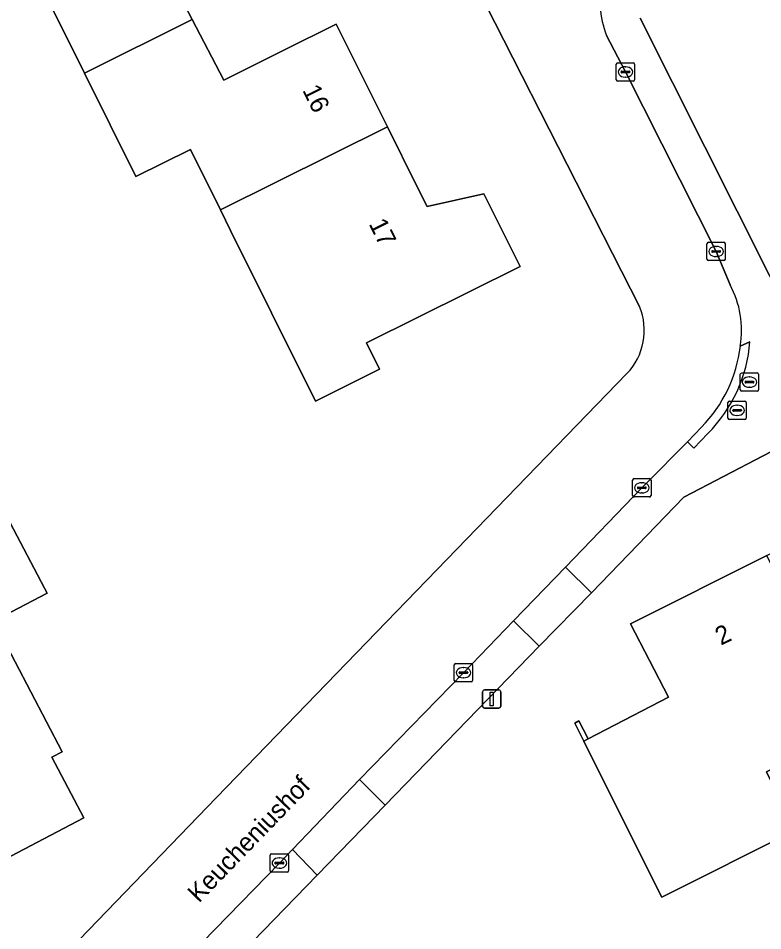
# Model space of a CAD drawing. Extents: x 162722 to 165104, y 384719 to 386284.
# Drawn here: x 163739.56 to 163780.16, y 384930.12 to 384979.9 of the extents above; entities that cross this region are included whole.
import ezdxf

# ---------------------------------------------------------------- set-up
doc = ezdxf.new("R2010")
doc.units = 0
for name, color, linetype in [('IMGEO_Erf', 7, 'Continuous'), ('IMGEO_Kolk', 7, 'Continuous'), ('IMGEO_Lichtmast', 7, 'Continuous'), ('IMGEO_Muur', 7, 'Continuous'), ('IMGEO_Openbare_ruimte_label', 7, 'Continuous'), ('IMGEO_Pand', 7, 'Continuous'), ('IMGEO_Pand_nummerreeks', 7, 'Continuous'), ('IMGEO_Parkeervlak_open', 7, 'Continuous'), ('IMGEO_Rijbaan_lokaal_open', 7, 'Continuous'), ('IMGEO_Rioolput', 7, 'Continuous'), ('IMGEO_Voetpad_open', 7, 'Continuous')]:
    doc.layers.add(name, color=color, linetype=linetype)

msp = doc.modelspace()

# ---------------------------------------------------------------- linework, layer by layer
at = {"layer": 'IMGEO_Erf'}
for points in [[(163773.45, 384964.172), (163757.669, 384995.182)], [(163747.308, 384983.144), (163749.036, 384979.836), (163750.763, 384976.531), (163754.038, 384978.16), (163756.905, 384979.586), (163759.69, 384973.984), (163761.287, 384970.773), (163761.856, 384969.629), (163764.958, 384970.319), (163766.926, 384966.361), (163758.55, 384962.196), (163759.265, 384960.758), (163755.768, 384959.019), (163753.371, 384963.839), (163751.144, 384968.317), (163750.581, 384969.45), (163748.947, 384972.736), (163745.975, 384971.259), (163743.164, 384976.913), (163740.366, 384982.54)], [(163773.478, 384979.9), (163782.291, 384962.358), (163782.404, 384962.416), (163802.16, 384972.581), (163804.226, 384968.418), (163784.518, 384958.283), (163775.869, 384953.781), (163770.816, 384948.556), (163767.966, 384945.654), (163759.567, 384936.98), (163755.864, 384933.157), (163744.141, 384921.063)], [(163739.897, 384926.539), (163750.364, 384937.388), (163772.76, 384960.515)]]:
    msp.add_lwpolyline(points, dxfattribs=at)
for points in [[(163774.653, 384931.962), (163772.706, 384935.862), (163770.404, 384940.472), (163769.914, 384941.454), (163770.139, 384941.571), (163770.645, 384940.597), (163775.023, 384942.872), (163772.946, 384946.868), (163780.388, 384950.584), (163787.828, 384954.299), (163788.941, 384952.07), (163791.108, 384947.731), (163796.82, 384950.584), (163794.653, 384954.922), (163794.885, 384955.038), (163797.052, 384950.7), (163800.045, 384944.704), (163790.533, 384939.954), (163788.967, 384943.091), (163785.094, 384941.157), (163780.367, 384938.797), (163781.958, 384935.61)], [(163739.111, 384952.379), (163740.984, 384948.815), (163741.129, 384948.539), (163739.187, 384947.518), (163738.217, 384947.008), (163738.524, 384946.424), (163741.959, 384939.889), (163741.39, 384939.59), (163743.129, 384936.283), (163737.685, 384933.421), (163735.947, 384936.728), (163733.919, 384935.662), (163731.932, 384939.443), (163730.365, 384942.425), (163729.381, 384941.909), (163727.176, 384946.104), (163737.169, 384951.358)]]:
    msp.add_lwpolyline(points, close=True, dxfattribs=at)
msp.add_arc((163770.267, 384962.879), 3.436, 316.5242, 22.1059, dxfattribs=at)
at = {"layer": 'IMGEO_Kolk'}
for p, q in [((163772.176, 384976.545), (163772.176, 384977.397)), ((163772.251, 384977.471), (163773.103, 384977.471)), ((163772.664, 384977.251), (163772.689, 384977.251)), ((163773.177, 384977.397), (163773.177, 384976.545)), ((163772.435, 384976.965), (163772.435, 384976.977)), ((163772.873, 384976.928), (163772.475, 384976.928)), ((163772.478, 384977.014), (163772.876, 384977.014)), ((163772.687, 384976.691), (163772.662, 384976.691)), ((163772.919, 384976.977), (163772.919, 384976.965)), ((163773.103, 384976.471), (163772.251, 384976.471)), ((163777.198, 384967.677), (163778.05, 384967.677)), ((163777.123, 384966.751), (163777.123, 384967.603)), ((163777.382, 384967.171), (163777.382, 384967.183)), ((163777.82, 384967.134), (163777.422, 384967.134)), ((163777.425, 384967.22), (163777.823, 384967.22)), ((163777.611, 384967.457), (163777.636, 384967.457)), ((163777.866, 384967.183), (163777.866, 384967.171)), ((163778.124, 384967.603), (163778.124, 384966.751)), ((163778.05, 384966.677), (163777.198, 384966.677)), ((163777.634, 384966.897), (163777.609, 384966.897)), ((163773.069, 384953.858), (163773.069, 384954.71)), ((163773.144, 384954.784), (163773.996, 384954.784)), ((163774.07, 384954.71), (163774.07, 384953.858)), ((163773.328, 384954.278), (163773.328, 384954.29)), ((163773.766, 384954.241), (163773.368, 384954.241)), ((163773.371, 384954.327), (163773.769, 384954.327)), ((163773.557, 384954.564), (163773.582, 384954.564)), ((163773.812, 384954.29), (163773.812, 384954.278)), ((163773.996, 384953.784), (163773.144, 384953.784)), ((163773.58, 384954.004), (163773.555, 384954.004)), ((163763.34, 384943.773), (163763.34, 384944.625)), ((163763.415, 384944.699), (163764.267, 384944.699)), ((163763.642, 384944.242), (163764.04, 384944.242)), ((163763.828, 384944.479), (163763.853, 384944.479)), ((163764.341, 384944.625), (163764.341, 384943.773)), ((163763.599, 384944.193), (163763.599, 384944.205)), ((163764.037, 384944.156), (163763.639, 384944.156)), ((163763.851, 384943.919), (163763.826, 384943.919)), ((163764.083, 384944.205), (163764.083, 384944.193)), ((163764.267, 384943.699), (163763.415, 384943.699)), ((163753.377, 384934.315), (163754.229, 384934.315)), ((163753.302, 384933.389), (163753.302, 384934.241)), ((163753.561, 384933.809), (163753.561, 384933.821)), ((163753.604, 384933.858), (163754.002, 384933.858)), ((163753.79, 384934.095), (163753.815, 384934.095)), ((163754.045, 384933.821), (163754.045, 384933.809)), ((163754.303, 384934.241), (163754.303, 384933.389)), ((163754.229, 384933.315), (163753.377, 384933.315)), ((163753.999, 384933.772), (163753.601, 384933.772)), ((163753.813, 384933.535), (163753.788, 384933.535))]:
    msp.add_line(p, q, dxfattribs=at)
for points in [[(163772.176, 384976.545), (163772.176, 384977.397)], [(163772.251, 384977.471), (163773.103, 384977.471)], [(163773.177, 384977.397), (163773.177, 384976.545)], [(163773.103, 384976.471), (163772.251, 384976.471)], [(163777.198, 384967.677), (163778.05, 384967.677)], [(163777.123, 384966.751), (163777.123, 384967.603)], [(163778.124, 384967.603), (163778.124, 384966.751)], [(163778.05, 384966.677), (163777.198, 384966.677)], [(163773.069, 384953.858), (163773.069, 384954.71)], [(163773.144, 384954.784), (163773.996, 384954.784)], [(163774.07, 384954.71), (163774.07, 384953.858)], [(163773.996, 384953.784), (163773.144, 384953.784)], [(163763.34, 384943.773), (163763.34, 384944.625)], [(163763.415, 384944.699), (163764.267, 384944.699)], [(163764.341, 384944.625), (163764.341, 384943.773)], [(163764.267, 384943.699), (163763.415, 384943.699)], [(163753.377, 384934.315), (163754.229, 384934.315)], [(163753.302, 384933.389), (163753.302, 384934.241)], [(163754.303, 384934.241), (163754.303, 384933.389)], [(163754.229, 384933.315), (163753.377, 384933.315)]]:
    msp.add_lwpolyline(points, dxfattribs=at)
for centre, radius, start, end in [((163772.253, 384977.395), 0.0765, 91.552, 178.448), ((163772.253, 384977.395), 0.0765, 91.552, 178.448), ((163773.101, 384977.395), 0.0765, 1.552, 88.448), ((163773.101, 384977.395), 0.0765, 1.552, 88.448), ((163772.475, 384976.974), 0.0403, 85.8775, 175.7526), ((163772.472, 384976.964), 0.0366, 178.938, 274.7102), ((163772.876, 384976.971), 0.043, 264.8664, 352.4533), ((163772.88, 384976.976), 0.0386, 1.7309, 96.639), ((163772.253, 384976.547), 0.0765, 181.552, 268.448), ((163772.253, 384976.547), 0.0765, 181.552, 268.448), ((163773.101, 384976.547), 0.0765, 271.552, 358.448), ((163773.101, 384976.547), 0.0765, 271.552, 358.448), ((163777.2, 384967.601), 0.0765, 91.552, 178.448), ((163777.2, 384967.601), 0.0765, 91.552, 178.448), ((163778.048, 384967.601), 0.0765, 1.552, 88.448), ((163778.048, 384967.601), 0.0765, 1.552, 88.448), ((163777.422, 384967.18), 0.0403, 85.8775, 175.7526), ((163777.419, 384967.17), 0.0366, 178.938, 274.7102), ((163777.823, 384967.177), 0.043, 264.8664, 352.4533), ((163777.827, 384967.182), 0.0386, 1.7309, 96.639), ((163777.2, 384966.753), 0.0765, 181.552, 268.448), ((163777.2, 384966.753), 0.0765, 181.552, 268.448), ((163778.048, 384966.753), 0.0765, 271.552, 358.448), ((163778.048, 384966.753), 0.0765, 271.552, 358.448), ((163773.146, 384954.708), 0.0765, 91.552, 178.448), ((163773.146, 384954.708), 0.0765, 91.552, 178.448), ((163773.994, 384954.708), 0.0765, 1.552, 88.448), ((163773.994, 384954.708), 0.0765, 1.552, 88.448), ((163773.368, 384954.287), 0.0403, 85.8775, 175.7526), ((163773.365, 384954.277), 0.0366, 178.938, 274.7102), ((163773.769, 384954.284), 0.043, 264.8664, 352.4533), ((163773.773, 384954.289), 0.0386, 1.7309, 96.639), ((163773.146, 384953.86), 0.0765, 181.552, 268.448), ((163773.146, 384953.86), 0.0765, 181.552, 268.448), ((163773.994, 384953.86), 0.0765, 271.552, 358.448), ((163773.994, 384953.86), 0.0765, 271.552, 358.448), ((163763.417, 384944.623), 0.0765, 91.552, 178.448), ((163763.417, 384944.623), 0.0765, 91.552, 178.448), ((163763.639, 384944.202), 0.0403, 85.8775, 175.7526), ((163764.044, 384944.204), 0.0386, 1.7309, 96.639), ((163764.265, 384944.623), 0.0765, 1.552, 88.448), ((163764.265, 384944.623), 0.0765, 1.552, 88.448), ((163763.417, 384943.775), 0.0765, 181.552, 268.448), ((163763.417, 384943.775), 0.0765, 181.552, 268.448), ((163763.636, 384944.192), 0.0366, 178.938, 274.7102), ((163764.04, 384944.199), 0.043, 264.8664, 352.4533), ((163764.265, 384943.775), 0.0765, 271.552, 358.448), ((163764.265, 384943.775), 0.0765, 271.552, 358.448), ((163753.379, 384934.239), 0.0765, 91.552, 178.448), ((163753.379, 384934.239), 0.0765, 91.552, 178.448), ((163754.227, 384934.239), 0.0765, 1.552, 88.448), ((163754.227, 384934.239), 0.0765, 1.552, 88.448), ((163753.601, 384933.818), 0.0403, 85.8775, 175.7526), ((163753.598, 384933.808), 0.0366, 178.938, 274.7102), ((163754.002, 384933.815), 0.043, 264.8664, 352.4533), ((163754.006, 384933.82), 0.0386, 1.7309, 96.639), ((163753.379, 384933.391), 0.0765, 181.552, 268.448), ((163753.379, 384933.391), 0.0765, 181.552, 268.448), ((163754.227, 384933.391), 0.0765, 271.552, 358.448), ((163754.227, 384933.391), 0.0765, 271.552, 358.448)]:
    msp.add_arc(centre, radius, start, end, dxfattribs=at)
for centre, major_axis, ratio, start_param, end_param in [((163772.663, 384976.971), (-0.387, 0.002), 0.722429, 4.712389, 7.853982), ((163772.688, 384976.971), (-0.39, 0.002), 0.717154, 1.570796, 4.712389), ((163777.61, 384967.177), (-0.387, 0.002), 0.722429, 4.712389, 7.853982), ((163777.635, 384967.177), (-0.39, 0.002), 0.717154, 1.570796, 4.712389), ((163773.556, 384954.284), (-0.387, 0.002), 0.722429, 4.712389, 7.853982), ((163773.581, 384954.284), (-0.39, 0.002), 0.717154, 1.570796, 4.712389), ((163763.827, 384944.199), (-0.387, 0.002), 0.722429, 4.712389, 7.853982), ((163763.852, 384944.199), (-0.39, 0.002), 0.717154, 1.570796, 4.712389), ((163753.789, 384933.815), (-0.387, 0.002), 0.722429, 4.712389, 7.853982), ((163753.814, 384933.815), (-0.39, 0.002), 0.717154, 1.570796, 4.712389)]:
    msp.add_ellipse(centre, major_axis=major_axis, ratio=ratio, start_param=start_param, end_param=end_param, dxfattribs=at)
at = {"layer": 'IMGEO_Lichtmast'}
for p, q in [((163764.983, 384943.264), (163765.773, 384943.264)), ((163765.773, 384943.264), (163764.983, 384943.264)), ((163764.883, 384942.364), (163764.883, 384943.164)), ((163764.883, 384943.164), (163764.883, 384942.364)), ((163765.873, 384943.164), (163765.873, 384942.364)), ((163765.873, 384942.364), (163765.873, 384943.164)), ((163765.773, 384942.264), (163764.983, 384942.264)), ((163764.983, 384942.264), (163765.773, 384942.264))]:
    msp.add_line(p, q, dxfattribs=at)
msp.add_lwpolyline([(163765.303, 384943.139), (163765.453, 384943.139), (163765.453, 384942.389), (163765.303, 384942.389), (163765.303, 384943.139)], dxfattribs=at)
for centre, start, end in [((163764.983, 384943.164), 90, 180), ((163764.983, 384943.164), 90, 180), ((163765.773, 384943.164), 0, 90), ((163765.773, 384943.164), 360, 90), ((163764.983, 384942.364), 180, 270), ((163764.983, 384942.364), 180, 270), ((163765.773, 384942.364), 270, 0), ((163765.773, 384942.364), 270, 0)]:
    msp.add_arc(centre, 0.1, start, end, dxfattribs=at)
at = {"layer": 'IMGEO_Muur'}
msp.add_lwpolyline([(163770.404, 384940.472), (163770.645, 384940.597), (163770.139, 384941.571), (163769.914, 384941.454)], close=True, dxfattribs=at)
at = {"layer": 'IMGEO_Pand'}
for points in [[(163741.448, 384987.316), (163743.137, 384983.918), (163740.366, 384982.54), (163743.164, 384976.913), (163749.036, 384979.836), (163747.308, 384983.144), (163750.717, 384984.839), (163753.45, 384986.198), (163750.625, 384991.88)], [(163759.69, 384973.984), (163756.905, 384979.586), (163754.038, 384978.16), (163750.763, 384976.531), (163749.036, 384979.836), (163743.164, 384976.913), (163745.975, 384971.259), (163748.947, 384972.736), (163750.581, 384969.45)], [(163753.371, 384963.839), (163755.768, 384959.019), (163759.265, 384960.758), (163758.55, 384962.196), (163766.926, 384966.361), (163764.958, 384970.319), (163761.856, 384969.629), (163761.287, 384970.773), (163759.69, 384973.984), (163750.581, 384969.45), (163751.144, 384968.317)], [(163738.524, 384946.424), (163738.217, 384947.008), (163739.187, 384947.518), (163741.129, 384948.539), (163740.984, 384948.815), (163739.111, 384952.379), (163737.169, 384951.358), (163727.176, 384946.104), (163729.381, 384941.909), (163730.365, 384942.425), (163731.932, 384939.443), (163733.919, 384935.662), (163735.947, 384936.728), (163737.685, 384933.421), (163743.129, 384936.283), (163741.39, 384939.59), (163741.959, 384939.889)], [(163780.388, 384950.584), (163772.946, 384946.868), (163775.023, 384942.872), (163770.645, 384940.597), (163770.404, 384940.472), (163772.706, 384935.862), (163774.653, 384931.962), (163781.958, 384935.61), (163780.367, 384938.797), (163785.094, 384941.157)]]:
    msp.add_lwpolyline(points, close=True, dxfattribs=at)
at = {"layer": 'IMGEO_Parkeervlak_open'}
for points in [[(163755.864, 384933.157), (163754.519, 384934.557), (163753.803, 384933.815), (163743.28, 384923.011), (163742.594, 384922.231)], [(163744.141, 384921.063), (163755.864, 384933.157)]]:
    msp.add_lwpolyline(points, dxfattribs=at)
at = {"layer": 'IMGEO_Rijbaan_lokaal_open'}
for points in [[(163766.126, 384990.376), (163764.463, 384993.662), (163762.509, 384997.523), (163758.942, 385004.57), (163758.54, 385004.374), (163754.144, 385002.139), (163755.228, 385000), (163757.669, 384995.182), (163773.45, 384964.172)], [(163778.389, 384965.352), (163777.624, 384967.177), (163772.677, 384976.971), (163771.635, 384978.961)], [(163772.76, 384960.515), (163750.364, 384937.388), (163739.897, 384926.539)], [(163763.841, 384944.199), (163766.576, 384947.033), (163769.406, 384949.952), (163773.57, 384954.284), (163773.782, 384954.495), (163776.052, 384956.795), (163776.818, 384957.602)], [(163742.594, 384922.231), (163743.28, 384923.011), (163753.803, 384933.815), (163754.519, 384934.557), (163758.179, 384938.378), (163763.841, 384944.199)]]:
    msp.add_lwpolyline(points, dxfattribs=at)
for centre, radius, start, end in [((163777.056, 384980.978), 5.784, 168.6516, 200.4096), ((163773.725, 384962.866), 5.285, 350.779, 28.062), ((163770.267, 384962.879), 3.436, 316.5242, 22.1059), ((163771.508, 384962.875), 7.484, 315.2038, 353.4333)]:
    msp.add_arc(centre, radius, start, end, dxfattribs=at)
at = {"layer": 'IMGEO_Rioolput'}
for p, q in [((163778.94, 384959.625), (163778.94, 384960.477)), ((163779.015, 384960.551), (163779.867, 384960.551)), ((163779.428, 384960.331), (163779.453, 384960.331)), ((163779.941, 384960.477), (163779.941, 384959.625)), ((163779.199, 384960.045), (163779.199, 384960.057)), ((163779.637, 384960.008), (163779.239, 384960.008)), ((163779.242, 384960.094), (163779.64, 384960.094)), ((163779.451, 384959.771), (163779.426, 384959.771)), ((163779.683, 384960.057), (163779.683, 384960.045)), ((163779.867, 384959.551), (163779.015, 384959.551)), ((163778.266, 384958.086), (163778.266, 384958.938)), ((163778.341, 384959.012), (163779.193, 384959.012)), ((163778.754, 384958.792), (163778.779, 384958.792)), ((163779.267, 384958.938), (163779.267, 384958.086)), ((163778.525, 384958.506), (163778.525, 384958.518)), ((163778.963, 384958.469), (163778.565, 384958.469)), ((163778.568, 384958.555), (163778.966, 384958.555)), ((163778.777, 384958.232), (163778.752, 384958.232)), ((163779.009, 384958.518), (163779.009, 384958.506)), ((163779.193, 384958.012), (163778.341, 384958.012))]:
    msp.add_line(p, q, dxfattribs=at)
for points in [[(163778.94, 384959.625), (163778.94, 384960.477)], [(163779.015, 384960.551), (163779.867, 384960.551)], [(163779.941, 384960.477), (163779.941, 384959.625)], [(163779.867, 384959.551), (163779.015, 384959.551)], [(163778.266, 384958.086), (163778.266, 384958.938)], [(163778.341, 384959.012), (163779.193, 384959.012)], [(163779.267, 384958.938), (163779.267, 384958.086)], [(163779.193, 384958.012), (163778.341, 384958.012)]]:
    msp.add_lwpolyline(points, dxfattribs=at)
for centre, radius, start, end in [((163779.017, 384960.475), 0.0765, 91.552, 178.448), ((163779.017, 384960.475), 0.0765, 91.552, 178.448), ((163779.865, 384960.475), 0.0765, 1.552, 88.448), ((163779.865, 384960.475), 0.0765, 1.552, 88.448), ((163779.239, 384960.054), 0.0403, 85.8775, 175.7526), ((163779.236, 384960.044), 0.0366, 178.938, 274.7102), ((163779.64, 384960.051), 0.043, 264.8664, 352.4533), ((163779.644, 384960.056), 0.0386, 1.7309, 96.639), ((163779.017, 384959.627), 0.0765, 181.552, 268.448), ((163779.017, 384959.627), 0.0765, 181.552, 268.448), ((163779.865, 384959.627), 0.0765, 271.552, 358.448), ((163779.865, 384959.627), 0.0765, 271.552, 358.448), ((163778.343, 384958.936), 0.0765, 91.552, 178.448), ((163778.343, 384958.936), 0.0765, 91.552, 178.448), ((163779.191, 384958.936), 0.0765, 1.552, 88.448), ((163779.191, 384958.936), 0.0765, 1.552, 88.448), ((163778.565, 384958.515), 0.0403, 85.8775, 175.7526), ((163778.562, 384958.505), 0.0366, 178.938, 274.7102), ((163778.966, 384958.512), 0.043, 264.8664, 352.4533), ((163778.97, 384958.517), 0.0386, 1.7309, 96.639), ((163778.343, 384958.088), 0.0765, 181.552, 268.448), ((163778.343, 384958.088), 0.0765, 181.552, 268.448), ((163779.191, 384958.088), 0.0765, 271.552, 358.448), ((163779.191, 384958.088), 0.0765, 271.552, 358.448)]:
    msp.add_arc(centre, radius, start, end, dxfattribs=at)
for centre, major_axis, ratio, start_param, end_param in [((163779.427, 384960.051), (-0.387, 0.002), 0.722429, 4.712389, 7.853982), ((163779.452, 384960.051), (-0.39, 0.002), 0.717154, 1.570796, 4.712389), ((163778.753, 384958.512), (-0.387, 0.002), 0.722429, 4.712389, 7.853982), ((163778.778, 384958.512), (-0.39, 0.002), 0.717154, 1.570796, 4.712389)]:
    msp.add_ellipse(centre, major_axis=major_axis, ratio=ratio, start_param=start_param, end_param=end_param, dxfattribs=at)
at = {"layer": 'IMGEO_Voetpad_open'}
for points in [[(163777.173, 384957.249), (163776.406, 384956.442), (163776.052, 384956.795), (163773.782, 384954.495), (163773.57, 384954.284), (163769.406, 384949.952), (163770.816, 384948.556), (163775.869, 384953.781), (163784.518, 384958.283), (163782.404, 384962.416), (163782.291, 384962.358), (163773.478, 384979.9)], [(163771.635, 384978.961), (163772.677, 384976.971), (163777.624, 384967.177), (163778.389, 384965.352)], [(163778.942, 384962.019), (163779.467, 384962.253)], [(163779.467, 384962.253), (163778.942, 384962.019)], [(163776.818, 384957.602), (163776.052, 384956.795), (163776.406, 384956.442), (163777.173, 384957.249)]]:
    msp.add_lwpolyline(points, dxfattribs=at)
for points in [[(163766.576, 384947.033), (163767.966, 384945.654), (163770.816, 384948.556), (163769.406, 384949.952)], [(163758.179, 384938.378), (163759.567, 384936.98), (163767.966, 384945.654), (163766.576, 384947.033), (163763.841, 384944.199)], [(163754.519, 384934.557), (163755.864, 384933.157), (163759.567, 384936.98), (163758.179, 384938.378)]]:
    msp.add_lwpolyline(points, close=True, dxfattribs=at)
for centre, radius, start, end in [((163777.056, 384980.978), 5.784, 168.6516, 200.4096), ((163773.725, 384962.866), 5.285, 350.779, 28.062), ((163771.509, 384962.873), 7.982, 315.2017, 355.5417), ((163771.509, 384962.873), 7.982, 315.2017, 355.5417), ((163771.508, 384962.875), 7.484, 315.2038, 353.4333)]:
    msp.add_arc(centre, radius, start, end, dxfattribs=at)

# ---------------------------------------------------------------- texts
at = {"layer": 'IMGEO_Openbare_ruimte_label'}
msp.add_text('Keucheniushof', height=1, rotation=45.9724, dxfattribs=at).set_placement((163749.415, 384931.596))
at = {"layer": 'IMGEO_Pand_nummerreeks'}
for s, rotation, p in [('16', 296.434, (163755.033, 384975.983)), ('17', 296.441, (163758.662, 384968.683)), ('2', 26.5337, (163777.883, 384945.667))]:
    msp.add_text(s, height=1, rotation=rotation, dxfattribs=at).set_placement(p)

doc.saveas('drawing.dxf')
